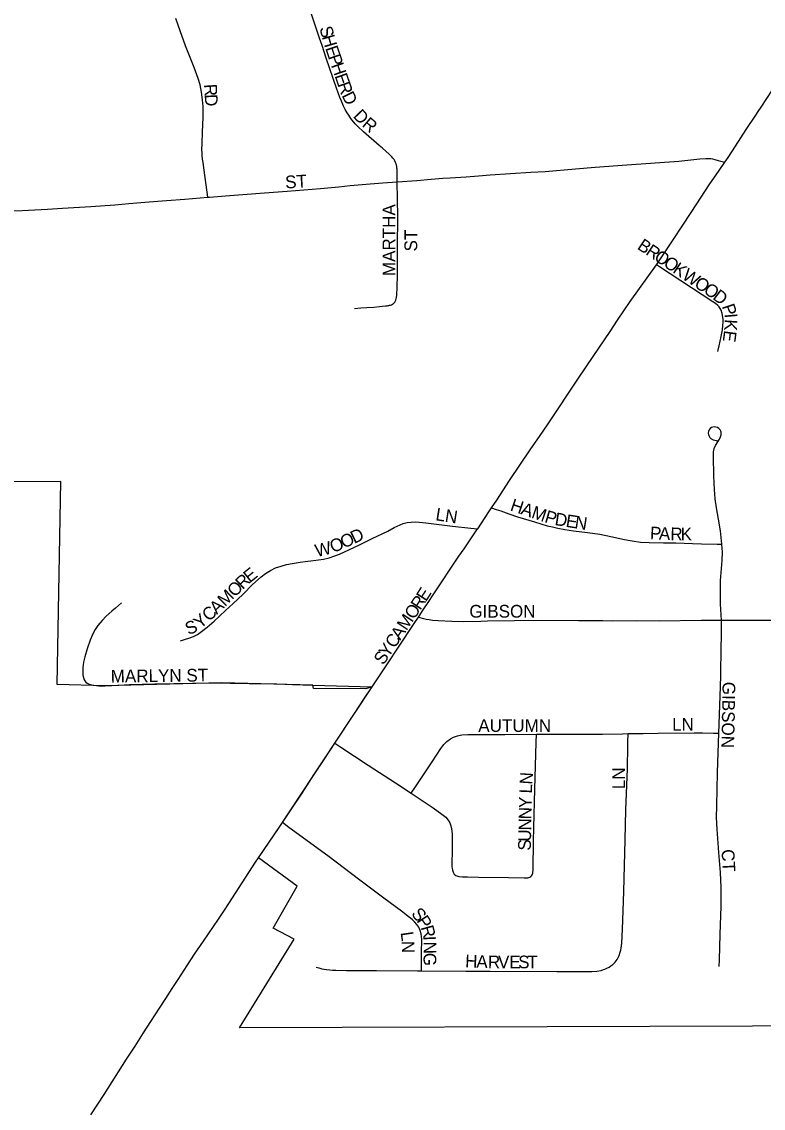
# Model space of a CAD drawing. Extents: x 1772825 to 1773716, y 1138558 to 1139032.
# Drawn here: x 1773337.87 to 1773348.9, y 1138845.8 to 1138861.97 of the extents above; entities that cross this region are included whole.
import ezdxf

# ---------------------------------------------------------------- set-up
doc = ezdxf.new("R2010")
doc.units = 0
for name, color, linetype in [('GM_X_City_Street', 7, 'Continuous'), ('GM_X_City_Street_Text', 7, 'Continuous'), ('GM_X_Corporation', 7, 'Continuous'), ('GM_X_County_Road', 7, 'Continuous')]:
    doc.layers.add(name, color=color, linetype=linetype)

msp = doc.modelspace()

# ---------------------------------------------------------------- linework, layer by layer
at = {"layer": 'GM_X_City_Street'}
for points in [[(1773343.456, 1138859.585), (1773343.456, 1138859.694), (1773343.456, 1138859.724), (1773343.456, 1138859.744), (1773343.454, 1138859.776), (1773343.452, 1138859.791), (1773343.45, 1138859.805), (1773343.448, 1138859.817), (1773343.446, 1138859.83), (1773343.444, 1138859.836), (1773343.44, 1138859.85), (1773343.435, 1138859.862), (1773343.43, 1138859.875), (1773343.418, 1138859.899), (1773343.408, 1138859.917), (1773343.392, 1138859.939), (1773343.378, 1138859.957), (1773343.338, 1138859.998), (1773343.235, 1138860.086), (1773343.188, 1138860.127), (1773342.953, 1138860.33), (1773342.868, 1138860.41), (1773342.832, 1138860.448), (1773342.786, 1138860.502), (1773342.765, 1138860.529), (1773342.734, 1138860.575), (1773342.711, 1138860.61), (1773342.695, 1138860.638), (1773342.682, 1138860.662), (1773342.658, 1138860.71), (1773342.625, 1138860.783), (1773342.601, 1138860.841), (1773342.551, 1138860.978), (1773342.401, 1138861.427), (1773342.337, 1138861.613), (1773342.3, 1138861.725), (1773342.234, 1138861.916), (1773342.17, 1138862.108)], [(1773340.64, 1138859.355), (1773340.582, 1138859.76), (1773340.566, 1138859.871), (1773340.559, 1138859.925), (1773340.555, 1138859.975), (1773340.552, 1138860.015), (1773340.551, 1138860.063), (1773340.552, 1138860.155), (1773340.558, 1138860.326), (1773340.566, 1138860.546), (1773340.566, 1138860.707), (1773340.56, 1138860.807), (1773340.545, 1138860.918), (1773340.522, 1138861.027), (1773340.494, 1138861.122), (1773340.433, 1138861.285), (1773340.307, 1138861.61), (1773340.224, 1138861.833), (1773340.194, 1138861.916), (1773340.16, 1138862.015)], [(1773348.329, 1138859.876), (1773348.379, 1138859.949), (1773348.489, 1138860.114), (1773348.649, 1138860.364), (1773348.79, 1138860.577), (1773348.826, 1138860.632), (1773348.873, 1138860.698), (1773349.041, 1138860.955), (1773349.147, 1138861.108), (1773349.231, 1138861.231), (1773349.464, 1138861.568), (1773349.484, 1138861.598)], [(1773343.456, 1138859.585), (1773343.749, 1138859.606), (1773343.959, 1138859.625), (1773344.133, 1138859.638), (1773344.244, 1138859.646), (1773344.48, 1138859.662), (1773344.666, 1138859.676), (1773344.839, 1138859.688), (1773345.446, 1138859.728), (1773345.657, 1138859.741), (1773346.111, 1138859.779), (1773346.402, 1138859.803), (1773346.874, 1138859.838), (1773347.645, 1138859.895), (1773347.959, 1138859.928), (1773348.048, 1138859.934), (1773348.087, 1138859.934), (1773348.121, 1138859.931), (1773348.148, 1138859.927), (1773348.18, 1138859.919), (1773348.231, 1138859.905), (1773348.329, 1138859.876)], [(1773347.312, 1138858.352), (1773347.393, 1138858.471), (1773347.552, 1138858.708), (1773347.715, 1138858.957), (1773347.912, 1138859.259), (1773348.096, 1138859.54), (1773348.245, 1138859.755), (1773348.329, 1138859.876)], [(1773340.64, 1138859.355), (1773340.665, 1138859.357), (1773340.9, 1138859.378), (1773341.482, 1138859.424), (1773341.817, 1138859.449), (1773342.312, 1138859.488), (1773342.585, 1138859.511), (1773342.758, 1138859.53), (1773343.052, 1138859.555), (1773343.241, 1138859.569), (1773343.456, 1138859.585)], [(1773342.818, 1138857.701), (1773342.915, 1138857.709), (1773343.006, 1138857.716), (1773343.107, 1138857.723), (1773343.19, 1138857.731), (1773343.28, 1138857.74), (1773343.304, 1138857.743), (1773343.321, 1138857.745), (1773343.331, 1138857.746), (1773343.342, 1138857.749), (1773343.355, 1138857.752), (1773343.372, 1138857.758), (1773343.384, 1138857.764), (1773343.394, 1138857.77), (1773343.405, 1138857.779), (1773343.412, 1138857.786), (1773343.417, 1138857.791), (1773343.421, 1138857.797), (1773343.426, 1138857.807), (1773343.431, 1138857.817), (1773343.433, 1138857.823), (1773343.437, 1138857.834), (1773343.44, 1138857.847), (1773343.443, 1138857.864), (1773343.448, 1138857.899), (1773343.452, 1138857.931), (1773343.456, 1138857.989), (1773343.457, 1138858.034), (1773343.461, 1138858.184), (1773343.461, 1138858.424), (1773343.46, 1138858.613), (1773343.463, 1138859.068), (1773343.456, 1138859.585)], [(1773337.638, 1138859.147), (1773337.741, 1138859.152), (1773337.877, 1138859.158), (1773338.25, 1138859.18), (1773338.473, 1138859.192), (1773338.895, 1138859.219), (1773339.254, 1138859.244), (1773339.464, 1138859.262), (1773339.7, 1138859.281), (1773340.021, 1138859.306), (1773340.294, 1138859.327), (1773340.64, 1138859.355)], [(1773344.861, 1138854.734), (1773344.937, 1138854.85), (1773345.128, 1138855.14), (1773345.444, 1138855.614), (1773345.571, 1138855.797), (1773345.702, 1138855.987), (1773346.154, 1138856.667), (1773346.373, 1138856.988), (1773346.623, 1138857.359), (1773346.733, 1138857.526), (1773346.923, 1138857.803), (1773347.312, 1138858.352)], [(1773348.226, 1138857.061), (1773348.246, 1138857.148), (1773348.259, 1138857.215), (1773348.275, 1138857.286), (1773348.294, 1138857.384), (1773348.302, 1138857.449), (1773348.308, 1138857.496), (1773348.306, 1138857.535), (1773348.303, 1138857.572), (1773348.292, 1138857.625), (1773348.274, 1138857.676), (1773348.262, 1138857.702), (1773348.246, 1138857.724), (1773348.225, 1138857.748), (1773348.194, 1138857.775), (1773348.153, 1138857.802), (1773347.358, 1138858.322), (1773347.312, 1138858.352)], [(1773348.286, 1138854.193), (1773348.282, 1138854.244), (1773348.268, 1138854.393), (1773348.238, 1138854.566), (1773348.205, 1138854.735), (1773348.187, 1138854.868), (1773348.177, 1138855.01), (1773348.167, 1138855.208), (1773348.161, 1138855.506), (1773348.163, 1138855.568), (1773348.172, 1138855.617), (1773348.191, 1138855.663), (1773348.25, 1138855.758), (1773348.265, 1138855.791), (1773348.274, 1138855.82), (1773348.277, 1138855.834), (1773348.276, 1138855.86), (1773348.271, 1138855.878), (1773348.259, 1138855.897), (1773348.242, 1138855.914), (1773348.219, 1138855.93), (1773348.196, 1138855.938), (1773348.173, 1138855.94), (1773348.152, 1138855.937), (1773348.131, 1138855.929), (1773348.111, 1138855.914), (1773348.096, 1138855.898), (1773348.087, 1138855.874), (1773348.085, 1138855.847), (1773348.088, 1138855.828), (1773348.092, 1138855.814), (1773348.096, 1138855.802), (1773348.102, 1138855.79), (1773348.109, 1138855.78), (1773348.115, 1138855.773), (1773348.122, 1138855.767), (1773348.13, 1138855.761), (1773348.138, 1138855.756), (1773348.146, 1138855.752), (1773348.157, 1138855.748), (1773348.18, 1138855.741), (1773348.204, 1138855.735), (1773348.217, 1138855.732)], [(1773344.652, 1138854.421), (1773344.654, 1138854.424), (1773344.821, 1138854.674), (1773344.861, 1138854.734)], [(1773344.861, 1138854.734), (1773344.929, 1138854.712), (1773345, 1138854.69), (1773345.117, 1138854.645), (1773345.247, 1138854.602), (1773345.497, 1138854.525), (1773345.689, 1138854.47), (1773345.764, 1138854.452), (1773345.847, 1138854.433), (1773345.951, 1138854.412), (1773346.078, 1138854.394), (1773346.286, 1138854.369), (1773346.47, 1138854.343), (1773346.633, 1138854.31), (1773346.838, 1138854.266), (1773346.952, 1138854.245), (1773347.078, 1138854.226), (1773347.203, 1138854.218), (1773347.416, 1138854.215), (1773347.602, 1138854.214), (1773347.85, 1138854.206), (1773347.985, 1138854.199), (1773348.217, 1138854.194), (1773348.286, 1138854.193)], [(1773340.231, 1138852.759), (1773340.304, 1138852.78), (1773340.357, 1138852.795), (1773340.426, 1138852.823), (1773340.484, 1138852.853), (1773340.545, 1138852.896), (1773340.627, 1138852.958), (1773340.73, 1138853.048), (1773340.901, 1138853.208), (1773341.008, 1138853.308), (1773341.162, 1138853.453), (1773341.304, 1138853.593), (1773341.429, 1138853.71), (1773341.498, 1138853.759), (1773341.57, 1138853.804), (1773341.646, 1138853.842), (1773341.727, 1138853.87), (1773341.809, 1138853.892), (1773341.893, 1138853.909), (1773342.013, 1138853.926), (1773342.086, 1138853.935), (1773342.209, 1138853.952), (1773342.357, 1138853.974), (1773342.443, 1138853.994), (1773342.527, 1138854.019), (1773342.599, 1138854.045), (1773342.734, 1138854.109), (1773342.893, 1138854.183), (1773343.081, 1138854.278), (1773343.315, 1138854.39), (1773343.412, 1138854.441), (1773343.545, 1138854.5), (1773343.603, 1138854.516), (1773343.662, 1138854.524), (1773343.734, 1138854.525), (1773343.882, 1138854.511), (1773344.277, 1138854.463), (1773344.549, 1138854.433), (1773344.652, 1138854.421)], [(1773343.772, 1138853.11), (1773343.782, 1138853.126), (1773343.843, 1138853.218), (1773343.924, 1138853.341), (1773343.99, 1138853.441), (1773344.373, 1138854.017), (1773344.45, 1138854.127), (1773344.652, 1138854.421)], [(1773348.279, 1138853.066), (1773348.265, 1138853.301), (1773348.264, 1138853.479), (1773348.268, 1138853.653), (1773348.29, 1138853.95), (1773348.294, 1138854.074), (1773348.286, 1138854.193)], [(1773339.351, 1138853.32), (1773339.311, 1138853.284), (1773339.266, 1138853.245), (1773339.209, 1138853.198), (1773339.125, 1138853.125), (1773339.067, 1138853.061), (1773339.001, 1138852.987), (1773338.96, 1138852.926), (1773338.925, 1138852.86), (1773338.887, 1138852.769), (1773338.842, 1138852.64), (1773338.81, 1138852.521), (1773338.799, 1138852.478), (1773338.789, 1138852.44), (1773338.784, 1138852.398), (1773338.779, 1138852.353), (1773338.778, 1138852.32), (1773338.777, 1138852.289), (1773338.78, 1138852.247), (1773338.786, 1138852.213), (1773338.794, 1138852.189), (1773338.809, 1138852.161), (1773338.823, 1138852.143), (1773338.842, 1138852.128), (1773338.863, 1138852.116), (1773338.885, 1138852.108), (1773338.943, 1138852.096), (1773339.017, 1138852.089), (1773339.105, 1138852.089), (1773339.316, 1138852.099), (1773339.465, 1138852.105), (1773339.851, 1138852.116), (1773340.41, 1138852.129), (1773340.721, 1138852.131), (1773340.97, 1138852.129), (1773341.255, 1138852.123), (1773341.664, 1138852.116), (1773341.9, 1138852.109), (1773342.202, 1138852.095), (1773343.082, 1138852.074)], [(1773343.082, 1138852.074), (1773343.313, 1138852.413), (1773343.476, 1138852.662), (1773343.707, 1138853.014), (1773343.772, 1138853.11)], [(1773343.772, 1138853.11), (1773343.845, 1138853.09), (1773343.888, 1138853.081), (1773343.929, 1138853.073), (1773343.979, 1138853.065), (1773344.067, 1138853.057), (1773344.266, 1138853.048), (1773344.441, 1138853.047), (1773344.702, 1138853.05), (1773344.801, 1138853.053), (1773345.198, 1138853.061), (1773345.596, 1138853.066), (1773346.154, 1138853.061), (1773346.253, 1138853.059), (1773346.513, 1138853.057), (1773346.662, 1138853.055), (1773347.01, 1138853.058), (1773347.358, 1138853.056), (1773347.98, 1138853.063), (1773348.279, 1138853.066)], [(1773348.239, 1138851.385), (1773348.265, 1138852.071), (1773348.269, 1138852.244), (1773348.278, 1138852.665), (1773348.282, 1138852.814), (1773348.279, 1138853.066)], [(1773348.279, 1138853.066), (1773348.327, 1138853.065), (1773348.638, 1138853.065), (1773348.873, 1138853.064), (1773349.133, 1138853.065), (1773349.294, 1138853.063), (1773349.741, 1138853.066), (1773349.94, 1138853.066), (1773350.076, 1138853.067), (1773350.262, 1138853.065), (1773350.348, 1138853.064), (1773350.522, 1138853.064), (1773350.766, 1138853.063)], [(1773343.662, 1138850.489), (1773343.726, 1138850.584), (1773343.974, 1138850.956), (1773344.104, 1138851.154), (1773344.151, 1138851.214), (1773344.195, 1138851.261), (1773344.247, 1138851.3), (1773344.293, 1138851.324), (1773344.355, 1138851.346), (1773344.419, 1138851.357), (1773344.508, 1138851.362), (1773345.055, 1138851.362), (1773345.529, 1138851.367)], [(1773343.662, 1138850.489), (1773343.99, 1138850.271), (1773344.122, 1138850.18), (1773344.177, 1138850.133), (1773344.215, 1138850.089), (1773344.238, 1138850.049), (1773344.255, 1138850.006), (1773344.265, 1138849.96), (1773344.272, 1138849.887), (1773344.273, 1138849.639), (1773344.267, 1138849.439), (1773344.269, 1138849.396), (1773344.272, 1138849.374), (1773344.277, 1138849.346), (1773344.287, 1138849.315), (1773344.304, 1138849.288), (1773344.329, 1138849.268), (1773344.371, 1138849.252), (1773344.425, 1138849.248), (1773344.504, 1138849.246), (1773344.663, 1138849.242), (1773345.111, 1138849.235), (1773345.346, 1138849.229), (1773345.4, 1138849.232), (1773345.429, 1138849.241), (1773345.442, 1138849.249), (1773345.454, 1138849.26), (1773345.464, 1138849.274), (1773345.47, 1138849.288), (1773345.474, 1138849.303), (1773345.478, 1138849.355), (1773345.485, 1138849.779), (1773345.489, 1138849.977), (1773345.504, 1138850.549), (1773345.525, 1138851.246), (1773345.529, 1138851.367)], [(1773343.817, 1138847.848), (1773344.477, 1138847.843), (1773344.837, 1138847.843), (1773345.832, 1138847.838), (1773346.142, 1138847.838), (1773346.354, 1138847.836), (1773346.428, 1138847.841), (1773346.489, 1138847.853), (1773346.524, 1138847.865), (1773346.547, 1138847.873), (1773346.577, 1138847.888), (1773346.608, 1138847.903), (1773346.633, 1138847.921), (1773346.664, 1138847.944), (1773346.699, 1138847.978), (1773346.727, 1138848.017), (1773346.744, 1138848.048), (1773346.757, 1138848.076), (1773346.774, 1138848.124), (1773346.784, 1138848.157), (1773346.79, 1138848.183), (1773346.798, 1138848.257), (1773346.808, 1138848.468), (1773346.817, 1138848.741), (1773346.827, 1138849.027), (1773346.846, 1138849.797), (1773346.858, 1138850.244), (1773346.881, 1138850.853), (1773346.889, 1138851.201), (1773346.889, 1138851.25), (1773346.89, 1138851.376)], [(1773345.529, 1138851.367), (1773345.601, 1138851.368), (1773346.024, 1138851.368), (1773346.508, 1138851.368), (1773346.806, 1138851.374), (1773346.89, 1138851.376)], [(1773346.89, 1138851.376), (1773347.117, 1138851.38), (1773347.341, 1138851.382), (1773347.875, 1138851.387), (1773347.999, 1138851.386), (1773348.161, 1138851.385), (1773348.239, 1138851.385)], [(1773348.248, 1138847.91), (1773348.25, 1138848.009), (1773348.259, 1138848.393), (1773348.275, 1138848.803), (1773348.274, 1138849.087), (1773348.265, 1138849.31), (1773348.242, 1138849.607), (1773348.216, 1138849.954), (1773348.209, 1138850.128), (1773348.21, 1138850.303), (1773348.222, 1138850.797), (1773348.239, 1138851.385)], [(1773342.529, 1138851.236), (1773342.619, 1138851.176), (1773343.024, 1138850.909), (1773343.43, 1138850.643), (1773343.662, 1138850.489)], [(1773343.817, 1138847.848), (1773343.818, 1138847.984), (1773343.819, 1138848.108), (1773343.821, 1138848.32), (1773343.818, 1138848.357), (1773343.812, 1138848.397), (1773343.799, 1138848.448), (1773343.778, 1138848.496), (1773343.749, 1138848.539), (1773343.715, 1138848.578), (1773343.685, 1138848.604), (1773343.653, 1138848.633), (1773343.62, 1138848.658), (1773343.538, 1138848.72), (1773343.239, 1138848.943), (1773342.901, 1138849.196), (1773342.425, 1138849.556), (1773341.844, 1138849.981), (1773341.747, 1138850.052)], [(1773342.25, 1138847.904), (1773342.289, 1138847.892), (1773342.336, 1138847.879), (1773342.403, 1138847.867), (1773342.453, 1138847.861), (1773342.492, 1138847.857), (1773342.543, 1138847.855), (1773342.7, 1138847.853), (1773343.147, 1138847.854), (1773343.756, 1138847.849), (1773343.817, 1138847.848)]]:
    msp.add_lwpolyline(points, dxfattribs=at)
at = {"layer": 'GM_X_Corporation'}
msp.add_lwpolyline([(1773353.322, 1138847.039), (1773341.111, 1138847), (1773341.921, 1138848.318), (1773341.61, 1138848.483), (1773341.969, 1138849.105), (1773341.393, 1138849.531), (1773341.717, 1138850.01), (1773342.529, 1138851.236), (1773343.082, 1138852.074), (1773342.987, 1138852.043), (1773342.208, 1138852.049), (1773342.202, 1138852.095), (1773340.845, 1138852.13), (1773339.105, 1138852.089), (1773338.398, 1138852.106), (1773338.452, 1138855.128), (1773336.618, 1138855.123)], dxfattribs=at)
at = {"layer": 'GM_X_County_Road'}
for points in [[(1773342.529, 1138851.236), (1773342.82, 1138851.674), (1773342.969, 1138851.903), (1773343.082, 1138852.074)], [(1773341.747, 1138850.052), (1773341.85, 1138850.201), (1773342.041, 1138850.491), (1773342.217, 1138850.762), (1773342.367, 1138850.99), (1773342.529, 1138851.236)], [(1773341.393, 1138849.531), (1773341.688, 1138849.967), (1773341.747, 1138850.052)], [(1773338.895, 1138845.705), (1773339.093, 1138846.006), (1773339.426, 1138846.531), (1773339.555, 1138846.728), (1773339.683, 1138846.927), (1773339.792, 1138847.093), (1773339.92, 1138847.291), (1773340.013, 1138847.438), (1773340.109, 1138847.583), (1773340.196, 1138847.718), (1773340.331, 1138847.927), (1773340.439, 1138848.094), (1773340.572, 1138848.289), (1773340.797, 1138848.617), (1773340.887, 1138848.752), (1773340.949, 1138848.848), (1773341.349, 1138849.462), (1773341.393, 1138849.531)]]:
    msp.add_lwpolyline(points, dxfattribs=at)

# ---------------------------------------------------------------- texts
at = {"layer": 'GM_X_City_Street_Text'}
for s, height, rotation, p in [('S', 0.189, 285.037, (1773342.297, 1138861.875)), ('H', 0.189, 286.2127, (1773342.333, 1138861.743)), ('E', 0.189, 288.5611, (1773342.382, 1138861.574)), ('P', 0.189, 288.9739, (1773342.425, 1138861.447)), ('H', 0.189, 288.9672, (1773342.468, 1138861.321)), ('E', 0.189, 288.9982, (1773342.522, 1138861.163)), ('R', 0.189, 273.7672, (1773340.581, 1138861.036)), ('R', 0.189, 288.9726, (1773342.566, 1138861.037)), ('D', 0.189, 272.274, (1773340.591, 1138860.887)), ('D', 0.189, 296.6002, (1773342.625, 1138860.87)), ('D', 0.189, 313.4544, (1773342.789, 1138860.556)), ('R', 0.189, 319.6121, (1773342.92, 1138860.42)), ('ST', 0.1894, 3.5746, (1773341.794, 1138859.485)), ('MARTHA', 0.1894, 90, (1773343.427, 1138858.183)), ('ST', 0.1894, 90, (1773343.753, 1138858.55)), ('B', 0.189, 326.3571, (1773347.015, 1138858.596)), ('R', 0.189, 326.3726, (1773347.14, 1138858.513)), ('O', 0.189, 326.3842, (1773347.265, 1138858.43)), ('O', 0.189, 326.3705, (1773347.404, 1138858.338)), ('K', 0.189, 326.3705, (1773347.543, 1138858.245)), ('W', 0.189, 326.3566, (1773347.682, 1138858.153)), ('O', 0.189, 326.3842, (1773347.862, 1138858.033)), ('O', 0.189, 326.3705, (1773348.001, 1138857.941)), ('D', 0.189, 323.235, (1773348.137, 1138857.85)), ('P', 0.189, 288.4868, (1773348.284, 1138857.735)), ('I', 0.189, 274.9016, (1773348.324, 1138857.62)), ('K', 0.189, 266.1728, (1773348.331, 1138857.545)), ('E', 0.189, 262.5191, (1773348.321, 1138857.382)), ('H', 0.189, 341.1297, (1773345.124, 1138854.699)), ('LN', 0.1894, 351.0327, (1773344.018, 1138854.552)), ('A', 0.189, 341.1297, (1773345.282, 1138854.645)), ('M', 0.189, 341.1254, (1773345.44, 1138854.591)), ('P', 0.189, 343.603, (1773345.637, 1138854.524)), ('D', 0.189, 350.7638, (1773345.791, 1138854.481)), ('E', 0.189, 351.0745, (1773345.956, 1138854.454)), ('N', 0.189, 351.0694, (1773346.088, 1138854.433)), ('O', 0.189, 24.2438, (1773342.66, 1138854.128)), ('D', 0.189, 25.6837, (1773342.817, 1138854.198)), ('P', 0.189, 357.5401, (1773347.214, 1138854.268)), ('A', 0.189, 357.5383, (1773347.347, 1138854.262)), ('R', 0.189, 358.6635, (1773347.518, 1138854.255)), ('K', 0.189, 359.9253, (1773347.672, 1138854.251)), ('W', 0.189, 13.6651, (1773342.259, 1138854.002)), ('O', 0.189, 21.8512, (1773342.498, 1138854.062)), ('E', 0.189, 38.8433, (1773341.262, 1138853.612)), ('R', 0.189, 43.231, (1773341.155, 1138853.512)), ('O', 0.189, 44.0913, (1773341.036, 1138853.397)), ('E', 0.189, 57.4837, (1773343.884, 1138853.331)), ('M', 0.189, 44.0943, (1773340.892, 1138853.258)), ('R', 0.189, 56.2539, (1773343.798, 1138853.203)), ('C', 0.189, 41.2722, (1773340.652, 1138853.036)), ('A', 0.189, 44.0754, (1773340.772, 1138853.142)), ('O', 0.189, 56.1062, (1773343.705, 1138853.064)), ('GIBSON', 0.1894, 0, (1773344.529, 1138853.102)), ('S', 0.189, 23.1304, (1773340.349, 1138852.839)), ('Y', 0.189, 41.0181, (1773340.526, 1138852.926)), ('M', 0.189, 56.0674, (1773343.593, 1138852.898)), ('A', 0.189, 56.1038, (1773343.5, 1138852.759)), ('Y', 0.189, 56.0907, (1773343.324, 1138852.497)), ('C', 0.189, 56.0993, (1773343.417, 1138852.635)), ('S', 0.189, 56.0826, (1773343.249, 1138852.386)), ('MARLYN ST', 0.1894, 0.7146, (1773339.194, 1138852.135)), ('GIBSON', 0.1894, 268.8989, (1773348.298, 1138852.149)), ('AUTUMN', 0.1894, 0, (1773344.662, 1138851.402)), ('LN', 0.1894, 0, (1773347.546, 1138851.419)), ('N', 0.189, 86.2819, (1773345.465, 1138850.615)), ('LN', 0.1894, 90, (1773346.844, 1138850.55)), ('L', 0.189, 87.5947, (1773345.459, 1138850.483)), ('Y', 0.189, 88.9569, (1773345.455, 1138850.267)), ('N', 0.189, 88.929, (1773345.452, 1138850.1)), ('N', 0.189, 88.9508, (1773345.449, 1138849.934)), ('U', 0.189, 88.9569, (1773345.446, 1138849.767)), ('S', 0.189, 88.9345, (1773345.443, 1138849.634)), ('CT', 0.1894, 273.1778, (1773348.281, 1138849.652)), ('S', 0.189, 309.9315, (1773343.655, 1138848.691)), ('P', 0.189, 303.4098, (1773343.737, 1138848.593)), ('R', 0.189, 285.6385, (1773343.804, 1138848.496)), ('L', 0.189, 278.1417, (1773343.505, 1138848.418)), ('N', 0.189, 270.7432, (1773343.523, 1138848.292)), ('I', 0.189, 272.4934, (1773343.843, 1138848.363)), ('N', 0.189, 270.4809, (1773343.847, 1138848.281)), ('G', 0.189, 270, (1773343.848, 1138848.115)), ('H', 0.189, 357.4203, (1773344.464, 1138847.902)), ('A', 0.189, 357.6284, (1773344.631, 1138847.894)), ('R', 0.189, 359.2339, (1773344.804, 1138847.887)), ('V', 0.189, 359.9478, (1773344.956, 1138847.885)), ('E', 0.189, 359.9956, (1773345.123, 1138847.885)), ('S', 0.189, 359.9956, (1773345.256, 1138847.885)), ('T', 0.189, 359.9956, (1773345.39, 1138847.885))]:
    msp.add_text(s, height=height, rotation=rotation, dxfattribs=at).set_placement(p)

doc.saveas('drawing.dxf')
